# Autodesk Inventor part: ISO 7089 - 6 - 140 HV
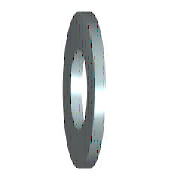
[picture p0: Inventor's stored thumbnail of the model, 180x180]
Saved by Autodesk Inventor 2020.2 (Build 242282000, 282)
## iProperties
Manager: www.cadconsulting.pl
Company: Fabian Stasiak CAD Consulting
Created: 2010-02
Part Number: ISO 7089 - 6 - 140 HV
Material: Spawana stal nierdzewna
Description: Podkładki okrągłe - Szereg normalny - Klasa dokładności A
Document SubType Name: Modeling
Standard: ISO 7089
Designer: F.Stasiak
Standard Revision: Second edition 2000-06-01
Standards Organization: ISO
Language: pl-PL
Size Designation: 6 - 140 HV
Categories: <MemberInstance><Categories><Category DisplayName="Mocowania" InternalName="e4da775c-781d-43d5-af7c-5136215cf5a6" Mnemonic="FSTN"><Category DisplayName="Podkład
Density: 8.08 g/cm^3
Appearance: Metal-Stal
IsCustomPart: 0
Author: F.Stasiak
Subject: Zbiór ćwiczeń. Autodesk Inventor 2020. Kurs podstawowy
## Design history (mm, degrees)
sketch "Sketch"
  geometry: C1 r 6 at (0, 0); C2 r 3.2 at (0, 0); 1 further point
  constraints: 2 centre point, 2 coincident
  dimensions: "d0" = 6.4 diameter of C2 (= SD1); "d1" = 12 diameter of C1 (= SD2)
extrude "Body" new body sketch "Sketch" distance "d2" = 1.6 (= SD); taper "d3" = 0 deg
workaxis "Work Axis1"
workplane "Work Plane1"
body "Solid1"
other parameters: "SD1" = 6.4 [user parameter; used in 1 equation term], "SD2" = 12 [user parameter; used in 1 equation term], "SD" = 1.6 [user parameter; used in 1 equation term], "d4" = 0, "d5" = 0, "d6" = 0, "d7" = 0, "NND" = 6 [user parameter]
